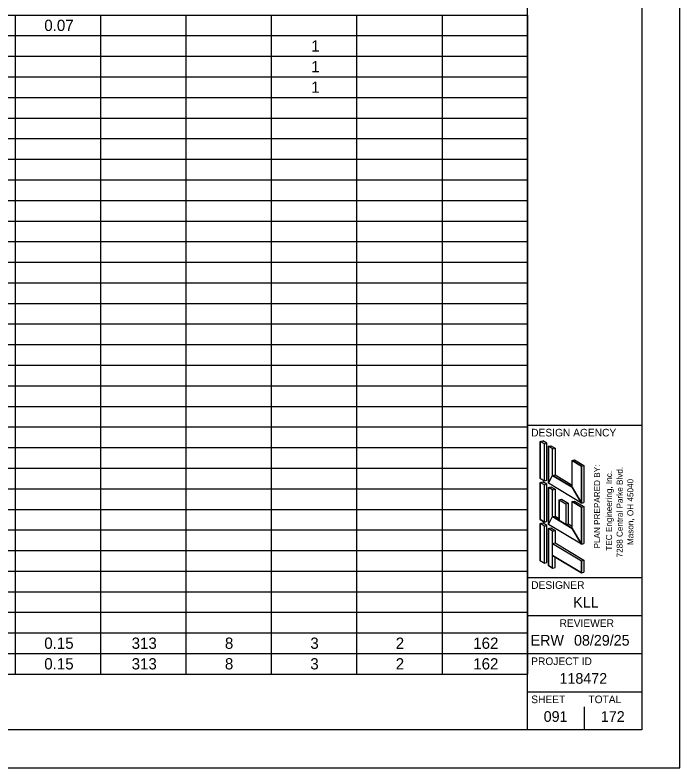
# Model space of a CAD drawing. Extents: x 0 to 34, y 0 to 22.
# Drawn here: x 25.28 to 34, y 0 to 9.88 of the extents above; entities that cross this region are included whole.
import ezdxf

# ---------------------------------------------------------------- set-up
doc = ezdxf.new("R2010")
doc.units = 0
for name, color, linetype in [('Default', 7, 'Continuous'), ('SH_Border', 7, 'Continuous'), ('SH_Cut_Line', 7, 'Continuous'), ('SH_Data', 7, 'Continuous'), ('SH_Text', 7, 'Continuous')]:
    doc.layers.add(name, color=color, linetype=linetype)

msp = doc.modelspace()

# ---------------------------------------------------------------- linework, layer by layer
at = {"layer": 'SH_Border'}
for p, q in [((32, 0.5), (32, 21.5)), ((32, 4.5), (33.5, 4.5)), ((32, 2.5), (33.5, 2.5)), ((32, 2), (33.5, 2)), ((32, 1.5), (33.5, 1.5)), ((32, 1), (33.5, 1))]:
    msp.add_line(p, q, dxfattribs=at)
msp.add_lwpolyline([(1.5, 21.5), (33.5, 21.5), (33.5, 0.5), (1.5, 0.5)], close=True, dxfattribs=at)
at = {"layer": 'SH_Cut_Line'}
msp.add_lwpolyline([(0, 0), (34, 0), (34, 22), (0, 22)], close=True, dxfattribs=at)
at = {"layer": 'SH_Data'}
for p, q in [((24.1627, 9.8794), (25.2823, 9.8794)), ((25.2823, 9.8794), (27.5215, 9.8794)), ((25.2823, 9.8794), (25.2823, 9.6092)), ((26.4019, 9.8794), (26.4019, 9.6092)), ((27.5215, 9.8794), (30.8804, 9.8794)), ((27.5215, 9.8794), (27.5215, 9.6092)), ((28.6411, 9.8794), (28.6411, 9.6092)), ((29.7608, 9.8794), (29.7608, 9.6092)), ((30.8804, 9.8794), (32, 9.8794)), ((30.8804, 9.8794), (30.8804, 9.6092)), ((32, 9.8794), (32, 9.6092)), ((24.1627, 9.6092), (25.2823, 9.6092)), ((25.2823, 9.6092), (27.5215, 9.6092)), ((25.2823, 9.6092), (25.2823, 9.3389)), ((26.4019, 9.6092), (26.4019, 9.3389)), ((27.5215, 9.6092), (30.8804, 9.6092)), ((27.5215, 9.6092), (27.5215, 9.3389)), ((28.6411, 9.6092), (28.6411, 9.3389)), ((29.7608, 9.6092), (29.7608, 9.3389)), ((30.8804, 9.6092), (32, 9.6092)), ((30.8804, 9.6092), (30.8804, 9.3389)), ((32, 9.6092), (32, 9.3389)), ((24.1627, 9.3389), (25.2823, 9.3389)), ((25.2823, 9.3389), (27.5215, 9.3389)), ((25.2823, 9.3389), (25.2823, 9.0687)), ((26.4019, 9.3389), (26.4019, 9.0687)), ((27.5215, 9.3389), (30.8804, 9.3389)), ((27.5215, 9.3389), (27.5215, 9.0687)), ((28.6411, 9.3389), (28.6411, 9.0687)), ((29.7608, 9.3389), (29.7608, 9.0687)), ((30.8804, 9.3389), (32, 9.3389)), ((30.8804, 9.3389), (30.8804, 9.0687)), ((32, 9.3389), (32, 9.0687)), ((24.1627, 9.0687), (25.2823, 9.0687)), ((25.2823, 9.0687), (27.5215, 9.0687)), ((25.2823, 9.0687), (25.2823, 8.7984)), ((26.4019, 9.0687), (26.4019, 8.7984)), ((27.5215, 9.0687), (30.8804, 9.0687)), ((27.5215, 9.0687), (27.5215, 8.7984)), ((28.6411, 9.0687), (28.6411, 8.7984)), ((29.7608, 9.0687), (29.7608, 8.7984)), ((30.8804, 9.0687), (32, 9.0687)), ((30.8804, 9.0687), (30.8804, 8.7984)), ((32, 9.0687), (32, 8.7984)), ((24.1627, 8.7984), (25.2823, 8.7984)), ((25.2823, 8.7984), (27.5215, 8.7984)), ((25.2823, 8.7984), (25.2823, 8.5282)), ((26.4019, 8.7984), (26.4019, 8.5282)), ((27.5215, 8.7984), (30.8804, 8.7984)), ((27.5215, 8.7984), (27.5215, 8.5282)), ((28.6411, 8.7984), (28.6411, 8.5282)), ((29.7608, 8.7984), (29.7608, 8.5282)), ((30.8804, 8.7984), (32, 8.7984)), ((30.8804, 8.7984), (30.8804, 8.5282)), ((32, 8.7984), (32, 8.5282)), ((24.1627, 8.5282), (25.2823, 8.5282)), ((25.2823, 8.5282), (27.5215, 8.5282)), ((25.2823, 8.5282), (25.2823, 8.2579)), ((26.4019, 8.5282), (26.4019, 8.2579)), ((27.5215, 8.5282), (30.8804, 8.5282)), ((27.5215, 8.5282), (27.5215, 8.2579)), ((28.6411, 8.5282), (28.6411, 8.2579)), ((29.7608, 8.5282), (29.7608, 8.2579)), ((30.8804, 8.5282), (32, 8.5282)), ((30.8804, 8.5282), (30.8804, 8.2579)), ((32, 8.5282), (32, 8.2579)), ((24.1627, 8.2579), (25.2823, 8.2579)), ((25.2823, 8.2579), (27.5215, 8.2579)), ((25.2823, 8.2579), (25.2823, 7.9876)), ((26.4019, 8.2579), (26.4019, 7.9876)), ((27.5215, 8.2579), (30.8804, 8.2579)), ((27.5215, 8.2579), (27.5215, 7.9876)), ((28.6411, 8.2579), (28.6411, 7.9876)), ((29.7608, 8.2579), (29.7608, 7.9876)), ((30.8804, 8.2579), (32, 8.2579)), ((30.8804, 8.2579), (30.8804, 7.9876)), ((32, 8.2579), (32, 7.9876)), ((24.1627, 7.9876), (25.2823, 7.9876)), ((25.2823, 7.9876), (27.5215, 7.9876)), ((25.2823, 7.9876), (25.2823, 7.7174)), ((26.4019, 7.9876), (26.4019, 7.7174)), ((27.5215, 7.9876), (30.8804, 7.9876)), ((27.5215, 7.9876), (27.5215, 7.7174)), ((28.6411, 7.9876), (28.6411, 7.7174)), ((29.7608, 7.9876), (29.7608, 7.7174)), ((30.8804, 7.9876), (32, 7.9876)), ((30.8804, 7.9876), (30.8804, 7.7174)), ((32, 7.9876), (32, 7.7174)), ((24.1627, 7.7174), (25.2823, 7.7174)), ((25.2823, 7.7174), (27.5215, 7.7174)), ((25.2823, 7.7174), (25.2823, 7.4471)), ((26.4019, 7.7174), (26.4019, 7.4471)), ((27.5215, 7.7174), (30.8804, 7.7174)), ((27.5215, 7.7174), (27.5215, 7.4471)), ((28.6411, 7.7174), (28.6411, 7.4471)), ((29.7608, 7.7174), (29.7608, 7.4471)), ((30.8804, 7.7174), (32, 7.7174)), ((30.8804, 7.7174), (30.8804, 7.4471)), ((32, 7.7174), (32, 7.4471)), ((24.1627, 7.4471), (25.2823, 7.4471)), ((25.2823, 7.4471), (27.5215, 7.4471)), ((25.2823, 7.4471), (25.2823, 7.1769)), ((26.4019, 7.4471), (26.4019, 7.1769)), ((27.5215, 7.4471), (30.8804, 7.4471)), ((27.5215, 7.4471), (27.5215, 7.1769)), ((28.6411, 7.4471), (28.6411, 7.1769)), ((29.7608, 7.4471), (29.7608, 7.1769)), ((30.8804, 7.4471), (32, 7.4471)), ((30.8804, 7.4471), (30.8804, 7.1769)), ((32, 7.4471), (32, 7.1769)), ((24.1627, 7.1769), (25.2823, 7.1769)), ((25.2823, 7.1769), (27.5215, 7.1769)), ((25.2823, 7.1769), (25.2823, 6.9066)), ((26.4019, 7.1769), (26.4019, 6.9066)), ((27.5215, 7.1769), (30.8804, 7.1769)), ((27.5215, 7.1769), (27.5215, 6.9066)), ((28.6411, 7.1769), (28.6411, 6.9066)), ((29.7608, 7.1769), (29.7608, 6.9066)), ((30.8804, 7.1769), (32, 7.1769)), ((30.8804, 7.1769), (30.8804, 6.9066)), ((32, 7.1769), (32, 6.9066)), ((24.1627, 6.9066), (25.2823, 6.9066)), ((25.2823, 6.9066), (27.5215, 6.9066)), ((25.2823, 6.9066), (25.2823, 6.6364)), ((26.4019, 6.9066), (26.4019, 6.6364)), ((27.5215, 6.9066), (30.8804, 6.9066)), ((27.5215, 6.9066), (27.5215, 6.6364)), ((28.6411, 6.9066), (28.6411, 6.6364)), ((29.7608, 6.9066), (29.7608, 6.6364)), ((30.8804, 6.9066), (32, 6.9066)), ((30.8804, 6.9066), (30.8804, 6.6364)), ((32, 6.9066), (32, 6.6364)), ((24.1627, 6.6364), (25.2823, 6.6364)), ((25.2823, 6.6364), (27.5215, 6.6364)), ((25.2823, 6.6364), (25.2823, 6.3661)), ((26.4019, 6.6364), (26.4019, 6.3661)), ((27.5215, 6.6364), (30.8804, 6.6364)), ((27.5215, 6.6364), (27.5215, 6.3661)), ((28.6411, 6.6364), (28.6411, 6.3661)), ((29.7608, 6.6364), (29.7608, 6.3661)), ((30.8804, 6.6364), (32, 6.6364)), ((30.8804, 6.6364), (30.8804, 6.3661)), ((32, 6.6364), (32, 6.3661)), ((24.1627, 6.3661), (25.2823, 6.3661)), ((25.2823, 6.3661), (27.5215, 6.3661)), ((25.2823, 6.3661), (25.2823, 5.8256)), ((26.4019, 6.3661), (26.4019, 5.8256)), ((27.5215, 6.3661), (30.8804, 6.3661)), ((27.5215, 6.3661), (27.5215, 5.8256)), ((28.6411, 6.3661), (28.6411, 5.8256)), ((29.7608, 6.3661), (29.7608, 5.8256)), ((30.8804, 6.3661), (32, 6.3661)), ((30.8804, 6.3661), (30.8804, 5.8256)), ((32, 6.3661), (32, 5.8256)), ((24.1627, 6.0959), (25.2823, 6.0959)), ((25.2823, 6.0959), (27.5215, 6.0959)), ((27.5215, 6.0959), (30.8804, 6.0959)), ((30.8804, 6.0959), (32, 6.0959)), ((24.1627, 5.8256), (25.2823, 5.8256)), ((25.2823, 5.8256), (27.5215, 5.8256)), ((25.2823, 5.8256), (25.2823, 5.5554)), ((26.4019, 5.8256), (26.4019, 5.5554)), ((27.5215, 5.8256), (30.8804, 5.8256)), ((27.5215, 5.8256), (27.5215, 5.5554)), ((28.6411, 5.8256), (28.6411, 5.5554)), ((29.7608, 5.8256), (29.7608, 5.5554)), ((30.8804, 5.8256), (32, 5.8256)), ((30.8804, 5.8256), (30.8804, 5.5554)), ((32, 5.8256), (32, 5.5554)), ((24.1627, 5.5554), (25.2823, 5.5554)), ((25.2823, 5.5554), (27.5215, 5.5554)), ((25.2823, 5.5554), (25.2823, 5.2851)), ((26.4019, 5.5554), (26.4019, 5.2851)), ((27.5215, 5.5554), (30.8804, 5.5554)), ((27.5215, 5.5554), (27.5215, 5.2851)), ((28.6411, 5.5554), (28.6411, 5.2851)), ((29.7608, 5.5554), (29.7608, 5.2851)), ((30.8804, 5.5554), (32, 5.5554)), ((30.8804, 5.5554), (30.8804, 5.2851)), ((32, 5.5554), (32, 5.2851)), ((24.1627, 5.2851), (25.2823, 5.2851)), ((25.2823, 5.2851), (27.5215, 5.2851)), ((25.2823, 5.2851), (25.2823, 5.0149)), ((26.4019, 5.2851), (26.4019, 5.0149)), ((27.5215, 5.2851), (30.8804, 5.2851)), ((27.5215, 5.2851), (27.5215, 5.0149)), ((28.6411, 5.2851), (28.6411, 5.0149)), ((29.7608, 5.2851), (29.7608, 5.0149)), ((30.8804, 5.2851), (32, 5.2851)), ((30.8804, 5.2851), (30.8804, 5.0149)), ((32, 5.2851), (32, 5.0149)), ((24.1627, 5.0149), (25.2823, 5.0149)), ((25.2823, 5.0149), (27.5215, 5.0149)), ((25.2823, 5.0149), (25.2823, 4.4744)), ((26.4019, 5.0149), (26.4019, 4.4744)), ((27.5215, 5.0149), (30.8804, 5.0149)), ((27.5215, 5.0149), (27.5215, 4.4744)), ((28.6411, 5.0149), (28.6411, 4.4744)), ((29.7608, 5.0149), (29.7608, 4.4744)), ((30.8804, 5.0149), (32, 5.0149)), ((30.8804, 5.0149), (30.8804, 4.4744)), ((32, 5.0149), (32, 4.4744)), ((24.1627, 4.7446), (25.2823, 4.7446)), ((25.2823, 4.7446), (27.5215, 4.7446)), ((27.5215, 4.7446), (30.8804, 4.7446)), ((30.8804, 4.7446), (32, 4.7446)), ((24.1627, 4.4744), (25.2823, 4.4744)), ((25.2823, 4.4744), (27.5215, 4.4744)), ((25.2823, 4.4744), (25.2823, 4.2041)), ((26.4019, 4.4744), (26.4019, 4.2041)), ((27.5215, 4.4744), (30.8804, 4.4744)), ((27.5215, 4.4744), (27.5215, 4.2041)), ((28.6411, 4.4744), (28.6411, 4.2041)), ((29.7608, 4.4744), (29.7608, 4.2041)), ((30.8804, 4.4744), (32, 4.4744)), ((30.8804, 4.4744), (30.8804, 4.2041)), ((32, 4.4744), (32, 4.2041)), ((24.1627, 4.2041), (25.2823, 4.2041)), ((25.2823, 4.2041), (27.5215, 4.2041)), ((25.2823, 4.2041), (25.2823, 3.9339)), ((26.4019, 4.2041), (26.4019, 3.9339)), ((27.5215, 4.2041), (30.8804, 4.2041)), ((27.5215, 4.2041), (27.5215, 3.9339)), ((28.6411, 4.2041), (28.6411, 3.9339)), ((29.7608, 4.2041), (29.7608, 3.9339)), ((30.8804, 4.2041), (32, 4.2041)), ((30.8804, 4.2041), (30.8804, 3.9339)), ((32, 4.2041), (32, 3.9339)), ((24.1627, 3.9339), (25.2823, 3.9339)), ((25.2823, 3.9339), (27.5215, 3.9339)), ((25.2823, 3.9339), (25.2823, 3.6636)), ((26.4019, 3.9339), (26.4019, 3.6636)), ((27.5215, 3.9339), (30.8804, 3.9339)), ((27.5215, 3.9339), (27.5215, 3.6636)), ((28.6411, 3.9339), (28.6411, 3.6636)), ((29.7608, 3.9339), (29.7608, 3.6636)), ((30.8804, 3.9339), (32, 3.9339)), ((30.8804, 3.9339), (30.8804, 3.6636)), ((32, 3.9339), (32, 3.6636)), ((24.1627, 3.6636), (25.2823, 3.6636)), ((25.2823, 3.6636), (27.5215, 3.6636)), ((25.2823, 3.6636), (25.2823, 3.1231)), ((26.4019, 3.6636), (26.4019, 3.1231)), ((27.5215, 3.6636), (30.8804, 3.6636)), ((27.5215, 3.6636), (27.5215, 3.1231)), ((28.6411, 3.6636), (28.6411, 3.1231)), ((29.7608, 3.6636), (29.7608, 3.1231)), ((30.8804, 3.6636), (32, 3.6636)), ((30.8804, 3.6636), (30.8804, 3.1231)), ((32, 3.6636), (32, 3.1231)), ((32.75, 3.5), (32.75, 3.5)), ((24.1627, 3.3933), (25.2823, 3.3933)), ((25.2823, 3.3933), (27.5215, 3.3933)), ((27.5215, 3.3933), (30.8804, 3.3933)), ((30.8804, 3.3933), (32, 3.3933)), ((24.1627, 3.1231), (25.2823, 3.1231)), ((25.2823, 3.1231), (27.5215, 3.1231)), ((25.2823, 3.1231), (25.2823, 2.8528)), ((26.4019, 3.1231), (26.4019, 2.8528)), ((27.5215, 3.1231), (30.8804, 3.1231)), ((27.5215, 3.1231), (27.5215, 2.8528)), ((28.6411, 3.1231), (28.6411, 2.8528)), ((29.7608, 3.1231), (29.7608, 2.8528)), ((30.8804, 3.1231), (32, 3.1231)), ((30.8804, 3.1231), (30.8804, 2.8528)), ((32, 3.1231), (32, 2.8528)), ((24.1627, 2.8528), (25.2823, 2.8528)), ((25.2823, 2.8528), (27.5215, 2.8528)), ((25.2823, 2.8528), (25.2823, 2.5826)), ((26.4019, 2.8528), (26.4019, 2.5826)), ((27.5215, 2.8528), (30.8804, 2.8528)), ((27.5215, 2.8528), (27.5215, 2.5826)), ((28.6411, 2.8528), (28.6411, 2.5826)), ((29.7608, 2.8528), (29.7608, 2.5826)), ((30.8804, 2.8528), (32, 2.8528)), ((30.8804, 2.8528), (30.8804, 2.5826)), ((32, 2.8528), (32, 2.5826)), ((24.1627, 2.5826), (25.2823, 2.5826)), ((25.2823, 2.5826), (27.5215, 2.5826)), ((25.2823, 2.5826), (25.2823, 2.3123)), ((26.4019, 2.5826), (26.4019, 2.3123)), ((27.5215, 2.5826), (30.8804, 2.5826)), ((27.5215, 2.5826), (27.5215, 2.3123)), ((28.6411, 2.5826), (28.6411, 2.3123)), ((29.7608, 2.5826), (29.7608, 2.3123)), ((30.8804, 2.5826), (32, 2.5826)), ((30.8804, 2.5826), (30.8804, 2.3123)), ((32, 2.5826), (32, 2.3123)), ((24.1627, 2.3123), (25.2823, 2.3123)), ((25.2823, 2.3123), (27.5215, 2.3123)), ((25.2823, 2.3123), (25.2823, 1.7718)), ((26.4019, 2.3123), (26.4019, 1.7718)), ((27.5215, 2.3123), (30.8804, 2.3123)), ((27.5215, 2.3123), (27.5215, 1.7718)), ((28.6411, 2.3123), (28.6411, 1.7718)), ((29.7608, 2.3123), (29.7608, 1.7718)), ((30.8804, 2.3123), (32, 2.3123)), ((30.8804, 2.3123), (30.8804, 1.7718)), ((32, 2.3123), (32, 1.7718)), ((24.1627, 2.0421), (25.2823, 2.0421)), ((25.2823, 2.0421), (27.5215, 2.0421)), ((27.5215, 2.0421), (30.8804, 2.0421)), ((30.8804, 2.0421), (32, 2.0421)), ((24.1627, 1.7718), (25.2823, 1.7718)), ((25.2823, 1.7718), (27.5215, 1.7718)), ((25.2823, 1.7718), (25.2823, 1.5016)), ((26.4019, 1.7718), (26.4019, 1.5016)), ((27.5215, 1.7718), (30.8804, 1.7718)), ((27.5215, 1.7718), (27.5215, 1.5016)), ((28.6411, 1.7718), (28.6411, 1.5016)), ((29.7608, 1.7718), (29.7608, 1.5016)), ((30.8804, 1.7718), (32, 1.7718)), ((30.8804, 1.7718), (30.8804, 1.5016)), ((32, 1.7718), (32, 1.5016)), ((24.1627, 1.5016), (25.2823, 1.5016)), ((25.2823, 1.5016), (27.5215, 1.5016)), ((25.2823, 1.5016), (25.2823, 1.2313)), ((26.4019, 1.5016), (26.4019, 1.2313)), ((27.5215, 1.5016), (30.8804, 1.5016)), ((27.5215, 1.5016), (27.5215, 1.2313)), ((28.6411, 1.5016), (28.6411, 1.2313)), ((29.7608, 1.5016), (29.7608, 1.2313)), ((30.8804, 1.5016), (32, 1.5016)), ((30.8804, 1.5016), (30.8804, 1.2313)), ((32, 1.5016), (32, 1.2313)), ((24.1627, 1.2313), (25.2823, 1.2313)), ((25.2823, 1.2313), (27.5215, 1.2313)), ((27.5215, 1.2313), (30.8804, 1.2313)), ((30.8804, 1.2313), (32, 1.2313)), ((32.75, 0.5), (32.75, 0.8)), ((32.375, 0.675), (32.375, 0.675))]:
    msp.add_line(p, q, dxfattribs=at)
at = {"layer": 'SH_Text'}
for p, q in [((32.1688, 4.2855), (32.2012, 4.2936)), ((32.1688, 3.7995), (32.1688, 4.2855)), ((32.2228, 4.2531), (32.1688, 4.2855)), ((32.2552, 4.2612), (32.2012, 4.2936)), ((32.2228, 4.2531), (32.2552, 4.2612)), ((32.2228, 3.7671), (32.2228, 4.2531)), ((32.2552, 3.7752), (32.2552, 4.2612)), ((32.2768, 4.2207), (32.3092, 4.2288)), ((32.3308, 4.1883), (32.2768, 4.2207)), ((32.2768, 3.7347), (32.2768, 4.2207)), ((32.3092, 4.2288), (32.3632, 4.1964)), ((32.3308, 4.1883), (32.3632, 4.1964)), ((32.3308, 3.8373), (32.3308, 4.1883)), ((32.3632, 4.1964), (32.3632, 3.8454)), ((32.5873, 4.0344), (32.6197, 4.0425)), ((32.5873, 3.6834), (32.5873, 4.0344)), ((32.7088, 3.9615), (32.5873, 4.0344)), ((32.6197, 4.0425), (32.7412, 3.9696)), ((32.7088, 3.9615), (32.7412, 3.9696)), ((32.7088, 3.4755), (32.7088, 3.9615)), ((32.7412, 3.9696), (32.7412, 3.4836)), ((32.2228, 3.7671), (32.1688, 3.7995)), ((32.2228, 3.7671), (32.2552, 3.7752)), ((32.3308, 3.8373), (32.3632, 3.8454)), ((32.5873, 3.6834), (32.3308, 3.8373)), ((32.3632, 3.8454), (32.5873, 3.7109)), ((32.1688, 3.7455), (32.2012, 3.7536)), ((32.1688, 3.2595), (32.1688, 3.7455)), ((32.2228, 3.7131), (32.1688, 3.7455)), ((32.2547, 3.7224), (32.2012, 3.7536)), ((32.2228, 3.7131), (32.2547, 3.7224)), ((32.2228, 3.2271), (32.2228, 3.7131)), ((32.2547, 3.2364), (32.2547, 3.7224)), ((32.7088, 3.4755), (32.2768, 3.7347)), ((32.2768, 3.6807), (32.3092, 3.6888)), ((32.2768, 3.1947), (32.2768, 3.6807)), ((32.3308, 3.6483), (32.2768, 3.6807)), ((32.3092, 3.6888), (32.3632, 3.6564)), ((32.3308, 3.6483), (32.3632, 3.6564)), ((32.3632, 3.6564), (32.3632, 3.3054)), ((32.3308, 3.2973), (32.3308, 3.6483)), ((32.4151, 3.5189), (32.4475, 3.527)), ((32.4151, 3.5189), (32.4151, 3.2466)), ((32.4151, 3.5189), (32.5029, 3.4663)), ((32.4475, 3.527), (32.5353, 3.4744)), ((32.5029, 3.4663), (32.5353, 3.4744)), ((32.5029, 3.4663), (32.5029, 3.194)), ((32.5353, 3.4744), (32.5353, 3.2021)), ((32.5873, 3.4944), (32.6197, 3.5025)), ((32.5873, 3.1434), (32.5873, 3.4944)), ((32.7088, 3.4215), (32.5873, 3.4944)), ((32.6197, 3.5025), (32.7412, 3.4296)), ((32.7088, 3.4755), (32.7412, 3.4836)), ((32.7088, 3.4215), (32.7412, 3.4296)), ((32.7088, 2.9355), (32.7088, 3.4215)), ((32.7412, 3.4296), (32.7412, 2.9436)), ((32.3308, 3.2973), (32.3632, 3.3054)), ((32.4151, 3.2466), (32.3308, 3.2973)), ((32.3632, 3.3054), (32.4151, 3.2742)), ((32.2228, 3.2271), (32.1688, 3.2595)), ((32.1688, 3.2055), (32.2007, 3.2148)), ((32.1688, 2.7195), (32.1688, 3.2055)), ((32.2228, 3.1731), (32.1688, 3.2055)), ((32.2552, 3.1812), (32.2007, 3.2148)), ((32.2223, 3.1733), (32.2552, 3.1812)), ((32.2228, 3.2271), (32.2547, 3.2364)), ((32.2228, 2.6871), (32.2228, 3.1731)), ((32.2552, 2.6952), (32.2552, 3.1812)), ((32.7088, 2.9355), (32.2768, 3.1947)), ((32.5029, 3.194), (32.5353, 3.2021)), ((32.5873, 3.1434), (32.5029, 3.194)), ((32.5353, 3.2021), (32.5873, 3.1709)), ((32.2768, 3.1407), (32.3087, 3.1514)), ((32.3308, 3.1083), (32.2768, 3.1407)), ((32.2768, 2.6547), (32.2768, 3.1407)), ((32.3087, 3.1514), (32.3632, 3.1164)), ((32.3308, 3.1083), (32.3632, 3.1164)), ((32.3308, 2.944), (32.3308, 3.1083)), ((32.3632, 3.1164), (32.3632, 2.9521)), ((32.3308, 2.944), (32.3632, 2.9521)), ((32.3308, 2.944), (32.7088, 2.7172)), ((32.3632, 2.9521), (32.7412, 2.7253)), ((32.7088, 2.9355), (32.7412, 2.9436)), ((32.3308, 2.7865), (32.7088, 2.5597)), ((32.3308, 2.6223), (32.3308, 2.7865)), ((32.3632, 2.6304), (32.3632, 2.7671)), ((32.2228, 2.6871), (32.1688, 2.7195)), ((32.2228, 2.6871), (32.2552, 2.6952)), ((32.7088, 2.7172), (32.7412, 2.7253)), ((32.7088, 2.5597), (32.7088, 2.7172)), ((32.7412, 2.7253), (32.7412, 2.5678)), ((32.3308, 2.6223), (32.2768, 2.6547)), ((32.3308, 2.6223), (32.3632, 2.6304)), ((32.7088, 2.5597), (32.7412, 2.5678))]:
    msp.add_line(p, q, dxfattribs=at)
for points in [[(32.1688, 3.7995), (32.2228, 3.7671), (32.2228, 4.2531), (32.1688, 4.2855)], [(32.2768, 3.7347), (32.3308, 3.8373), (32.3308, 4.1883), (32.2768, 4.2207)], [(32.7088, 3.4755), (32.5873, 3.6834), (32.5873, 4.0344), (32.7088, 3.9615)], [(32.2768, 3.7347), (32.3308, 3.8373), (32.5873, 3.6834), (32.7088, 3.4755)], [(32.1688, 3.2595), (32.2228, 3.2271), (32.2228, 3.7131), (32.1688, 3.7455)], [(32.2768, 3.1947), (32.3308, 3.2973), (32.3308, 3.6483), (32.2768, 3.6807)], [(32.4151, 3.2466), (32.4151, 3.5189), (32.5029, 3.4663), (32.5029, 3.194)], [(32.7088, 2.9355), (32.5873, 3.1434), (32.5873, 3.4944), (32.7088, 3.4215)], [(32.2768, 3.1947), (32.3308, 3.2973), (32.5873, 3.1434), (32.7088, 2.9355)], [(32.1688, 2.7195), (32.2228, 2.6871), (32.2228, 3.1731), (32.1688, 3.2055)], [(32.2768, 2.6547), (32.3308, 2.6223), (32.3308, 3.1083), (32.2768, 3.1407)], [(32.3308, 2.7865), (32.3308, 2.944), (32.7088, 2.7172), (32.7088, 2.5597)]]:
    msp.add_lwpolyline(points, close=True, dxfattribs=at)

# ---------------------------------------------------------------- texts
at = {"layer": 'Default'}
for s, p in [('PLAN PREPARED BY:', (32.9537, 2.8801)), ('TEC Engineering, Inc.', (33.1097, 2.8507)), ('7288 Central Parke Blvd.', (33.2497, 2.7622)), ('Mason, OH 45040', (33.3897, 2.9246))]:
    msp.add_text(s, height=0.08, rotation=90, dxfattribs=at).set_placement(p)
at = {"layer": 'SH_Data'}
for s, height, p in [('0.07', 0.148, (25.6653, 9.6703)), ('1', 0.148, (29.1663, 9.4)), ('1', 0.148, (29.1663, 9.1298)), ('1', 0.148, (29.1663, 8.8595)), ('DESIGN AGENCY', 0.1, (32.05, 4.35)), ('DESIGNER', 0.1, (32.05, 2.35)), ('KLL', 0.14, (32.6009, 2.105)), ('REVIEWER', 0.1, (32.4218, 1.85)), ('0.15', 0.148, (25.6648, 1.5627)), ('313', 0.148, (26.8107, 1.5627)), ('8', 0.148, (28.0337, 1.5627)), ('3', 0.148, (29.1534, 1.5627)), ('2', 0.148, (30.2738, 1.5627)), ('162', 0.148, (31.2899, 1.5627)), ('ERW', 0.14, (32.0425, 1.605)), ('08/29/25', 0.14, (32.611, 1.605)), ('0.15', 0.148, (25.6648, 1.2924)), ('313', 0.148, (26.8107, 1.2924)), ('8', 0.148, (28.0337, 1.2924)), ('3', 0.148, (29.1534, 1.2924)), ('2', 0.148, (30.2738, 1.2924)), ('162', 0.148, (31.2899, 1.2924)), ('PROJECT ID', 0.1, (32.05, 1.35)), ('118472', 0.14, (32.4209, 1.105)), ('SHEET', 0.1, (32.05, 0.85)), ('TOTAL', 0.1, (32.8, 0.85)), ('091', 0.14, (32.2134, 0.605)), ('172', 0.14, (32.9635, 0.605))]:
    msp.add_text(s, height=height, dxfattribs=at).set_placement(p)

doc.saveas('drawing.dxf')
